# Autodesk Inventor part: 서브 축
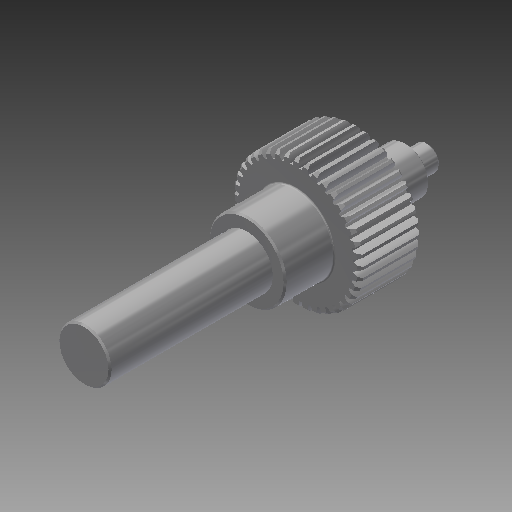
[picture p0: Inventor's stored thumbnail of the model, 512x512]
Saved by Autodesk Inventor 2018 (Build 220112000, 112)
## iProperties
Created: 2016-02
Part Number: 서브 축
Material: 강철, 연강
Document SubType Name: Modeling
Designer: mdu
Categories: <?xml version="1.0" encoding="UTF-16"?> <MemberInstance><Categories><FamilyTemplate><FamilyTemplateParameter ValueType="xs:double" Id="1" ObjectReferenceKey="da
Density: 7.86 g/cm^3
Appearance: 강철
CustomPartVersion: 1
Author: mdu
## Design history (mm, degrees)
sketch "Sketch1"
  geometry: C1 r 21 at (0, 0)
  constraints: 1 centre point
  dimensions: "d0" = 42 diameter of C1 (= da_da)
extrude "Extrusion1" new body sketch "Sketch1" distance "d1" = 20 (= da_b); taper "d2" = 0 deg
workplane "Work Plane2"
feature "피치 지름" dims "d4" = 10, "d5" = 0
workplane "Work Plane8"
workplane "Work Plane9"
chamfer "모따기1" distance "d49" = 1; stored, may be unused: second distance "d50" = 2, angle "d51" = 45 deg
sketch "스케치3"
  geometry: C1 r 12.5 at (0, 0); 1 further point
  constraints: 1 centre point, 1 coincident
  dimensions: "d52" = 25 diameter of C1
extrude "돌출2" join sketch "스케치3" distance "d53" = 16; taper "d54" = 0 deg
sketch "스케치4"
  geometry: C1 r 8.5 at (0, 0); 1 further point
  constraints: 1 centre point, 1 coincident
  dimensions: "d55" = 17 diameter of C1
extrude "돌출3" join sketch "스케치4" distance "d56" = 53; taper "d57" = 0 deg
sketch "스케치5"
  geometry: C1 r 7.5 at (0, 0); 1 further point
  constraints: 1 centre point, 1 coincident
  dimensions: "d62" = 15 diameter of C1
extrude "돌출4" join sketch "스케치5" distance "d63" = 16; taper "d64" = 0 deg
sketch "스케치6"
  geometry: C1 r 4 at (0, 0); 1 further point
  constraints: 1 centre point, 1 coincident
  dimensions: "d65" = 8 diameter of C1
extrude "돌출5" join sketch "스케치6" distance "d66" = 7; taper "d67" = 0 deg
chamfer "모따기2" distance "d58" = 0.5; stored, may be unused: second distance "d59" = 2, angle "d60" = 45 deg
fillet "모깎기1" dims "d61" = 0.5
feature "스퍼 기어" dims "da_b" = 20, "da_d" = 40, "da_aw" = 31, "da_da" = 42, "da_df" = 37.5, "da_dw" = 40, angle "da_beta" = 0 deg, "da_lefttooth" = 0, "da_righttooth" = 0
body "Solid1"
sketch "Sketch2"
  geometry: C1 r 21 at (0, 0) reference; C2 r 20 at (0, 0)
  constraints: 1 centre point, 1 coincident
  dimensions: "d3" = 40 diameter of C2 (= da_dw)
body "Srf1"
other parameters: "d16" = 31 (= da_aw), "d17" = 0, "d34" = 4.5 deg (computed from da_z), "d39" = 0, "d41" = 0, "d43" = 31 (= da_aw), "d46" = 31 (= da_aw), "d47" = 0, "d48" = 0
